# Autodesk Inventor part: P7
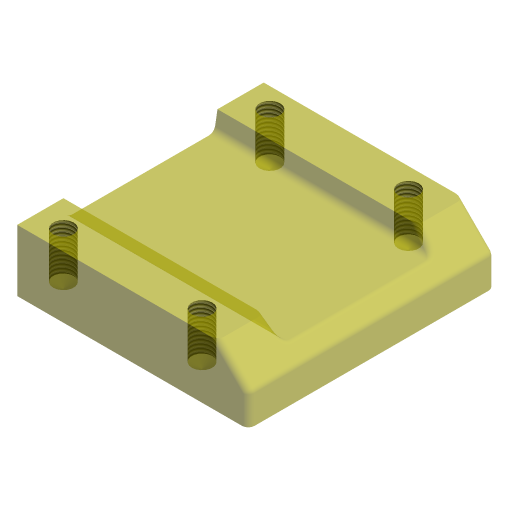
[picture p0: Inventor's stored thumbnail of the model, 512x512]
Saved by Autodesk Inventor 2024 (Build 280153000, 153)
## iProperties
Company: ATC
Shininess: 0.0
Length Units: 11269
Angle Units: 11279
Time Units: 11290
Mass Units: 11283
Length Display Precision: 3
Angle Display Precision: 2
Compacted: True
Created: 2023-03
Part Number: P7
Document SubType Name: Modeling
Designer: Andrzej Jaskulski
Material: Kurs-AJ
Density: 1 g/cm^3
Appearance: Przezroczyste — żółte
Checked By: A.J.
Engr Approved By: Andrzej Jaskulski
Mfg Approved By: Andrzej Jaskulski
Authority: A.J.
Density: 0.0
Volumn: 0.0
Area: 0.0
PropertySet Name: Model Information
Control State: 0
Master: False
Checked Out: False
Title: A.J.: Kurs R2024-MEP
Author: Andrzej Jaskulski
Revision Number: 1/24
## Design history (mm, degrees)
node "Extrusion1" dims "d0" = 0, "d1" = 20
  sketch "Sketch2"
    geometry: L1 (-60, 0)-(20, 0); L2 (20, 0)-(20, 75) reference; L3 (20, 75)-(-60, 75) reference; L4 (-60, 75)-(-60, 0)
    constraints: 8 end point, 2 parallel, 1 horizontal, 1 perpendicular, 1 vertical
    dimensions: "d3" = 80 distance of L1.start L1.end (= ROZSTAW); "d2" = 75 distance of L1.end L2.end
node "Chamfer1" dims "d4" = 10, "d5" = 10, "d29" = 45 deg
node "Extrusion2" dims "d6" = 0, "d7" = 10
  sketch "Sketch3"
    geometry: L1 (0, -20)-(80, -20) reference; L2 (80, 0)-(0, 0) reference; L3 (15, -20)-(16.058, -14); L4 (16.058, -14)-(63.942, -14); L5 (63.942, -14)-(65, -20); L6 (40, -14)-(40, -20)
    constraints: 8 end point, 2 midpoint, 2 point on line, 1 equal length, 1 parallel, 1 vertical
    dimensions: "d9" = 6 distance between parallel lines of L1 L4; "d8" = 100 deg angle of L4 L3; "d10" = 15 distance of L3.start L1.start; "d23" = 15 distance of L5.end L1.end
node "Fillet1" dims "d11" = 2, "d12" = 2
node "Hole1" dims "d17" = 118 deg, "d18" = 60 deg, "d19" = 2, "d20" = 4, "d21" = 15, "d22" = 6.64, "d28" = 6
  sketch "Sketch4"
    geometry: L1 (-53.5, 66.5)-(13.5, 66.5); L2 (13.5, 66.5)-(13.5, 21.5); L3 (13.5, 21.5)-(-53.5, 21.5); L4 (-53.5, 21.5)-(-53.5, 66.5); L5 (-42.264, 75)-(2.264, 75) reference; L6 (20, 75)-(20, 12.828) reference
    constraints: 8 end point, 2 parallel, 1 horizontal, 1 perpendicular
    dimensions: "d15" = 8.5 distance between parallel lines of L5 L1 (= odstęp2); "d14" = 6.5 distance between parallel lines of L2 L6 (= d26); "d16" = 67 distance of L1.start L1.end (= ROZSTAW - 2 x odstęp); "d13" = 45 distance between parallel lines of L3 L1 (= d25)
node "Bryła1"
node "Korpusy bryłowe"
node "Korpusy powierzchniowe"
other parameters: "d25" = 45, "d26" = 6.5, "d27" = 8.5, "odstęp" = 6.5 [user parameter; used in 1 equation term], "ROZSTAW" = 80 [user parameter; used in 2 equation terms], "odstęp2" = 8.5 [user parameter; used in 1 equation term]
